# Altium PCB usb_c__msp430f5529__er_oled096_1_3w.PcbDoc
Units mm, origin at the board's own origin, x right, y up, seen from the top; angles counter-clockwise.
Board outline 82 x 52 mm, 2 copper layers (Top, Bottom), stack 0 mm thick; 33 components, 35 nets, 214 pads, 89 vias.
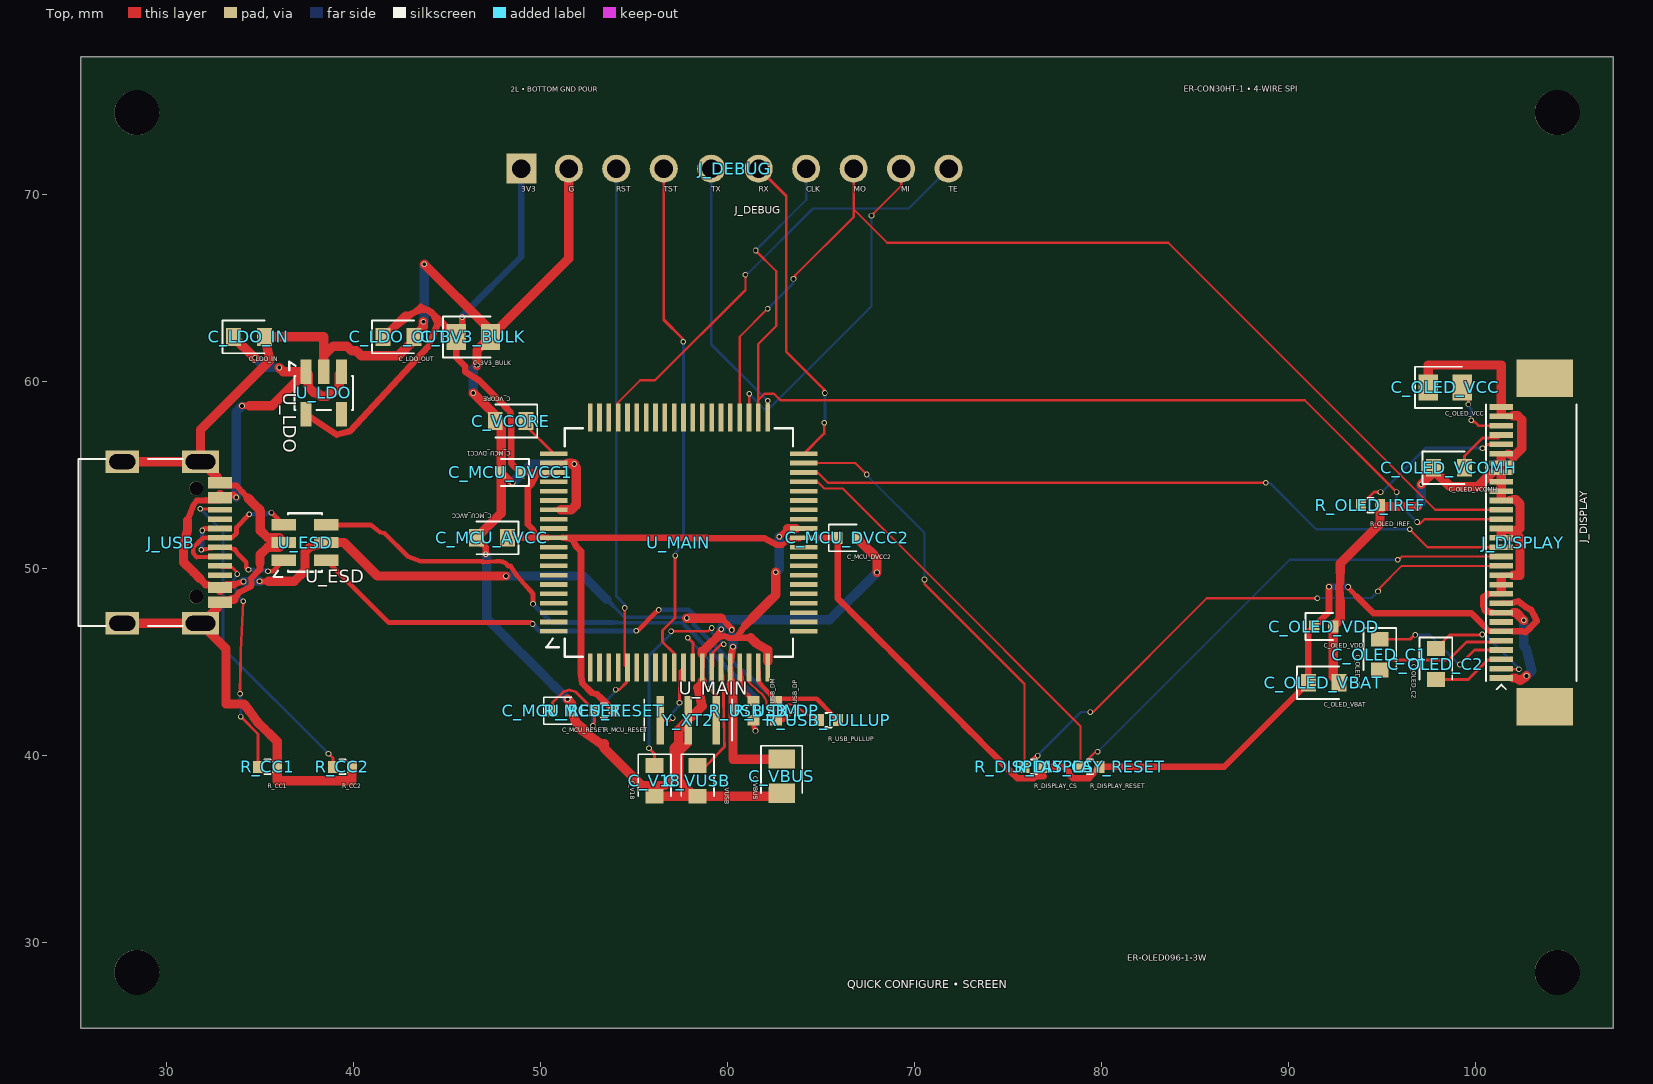
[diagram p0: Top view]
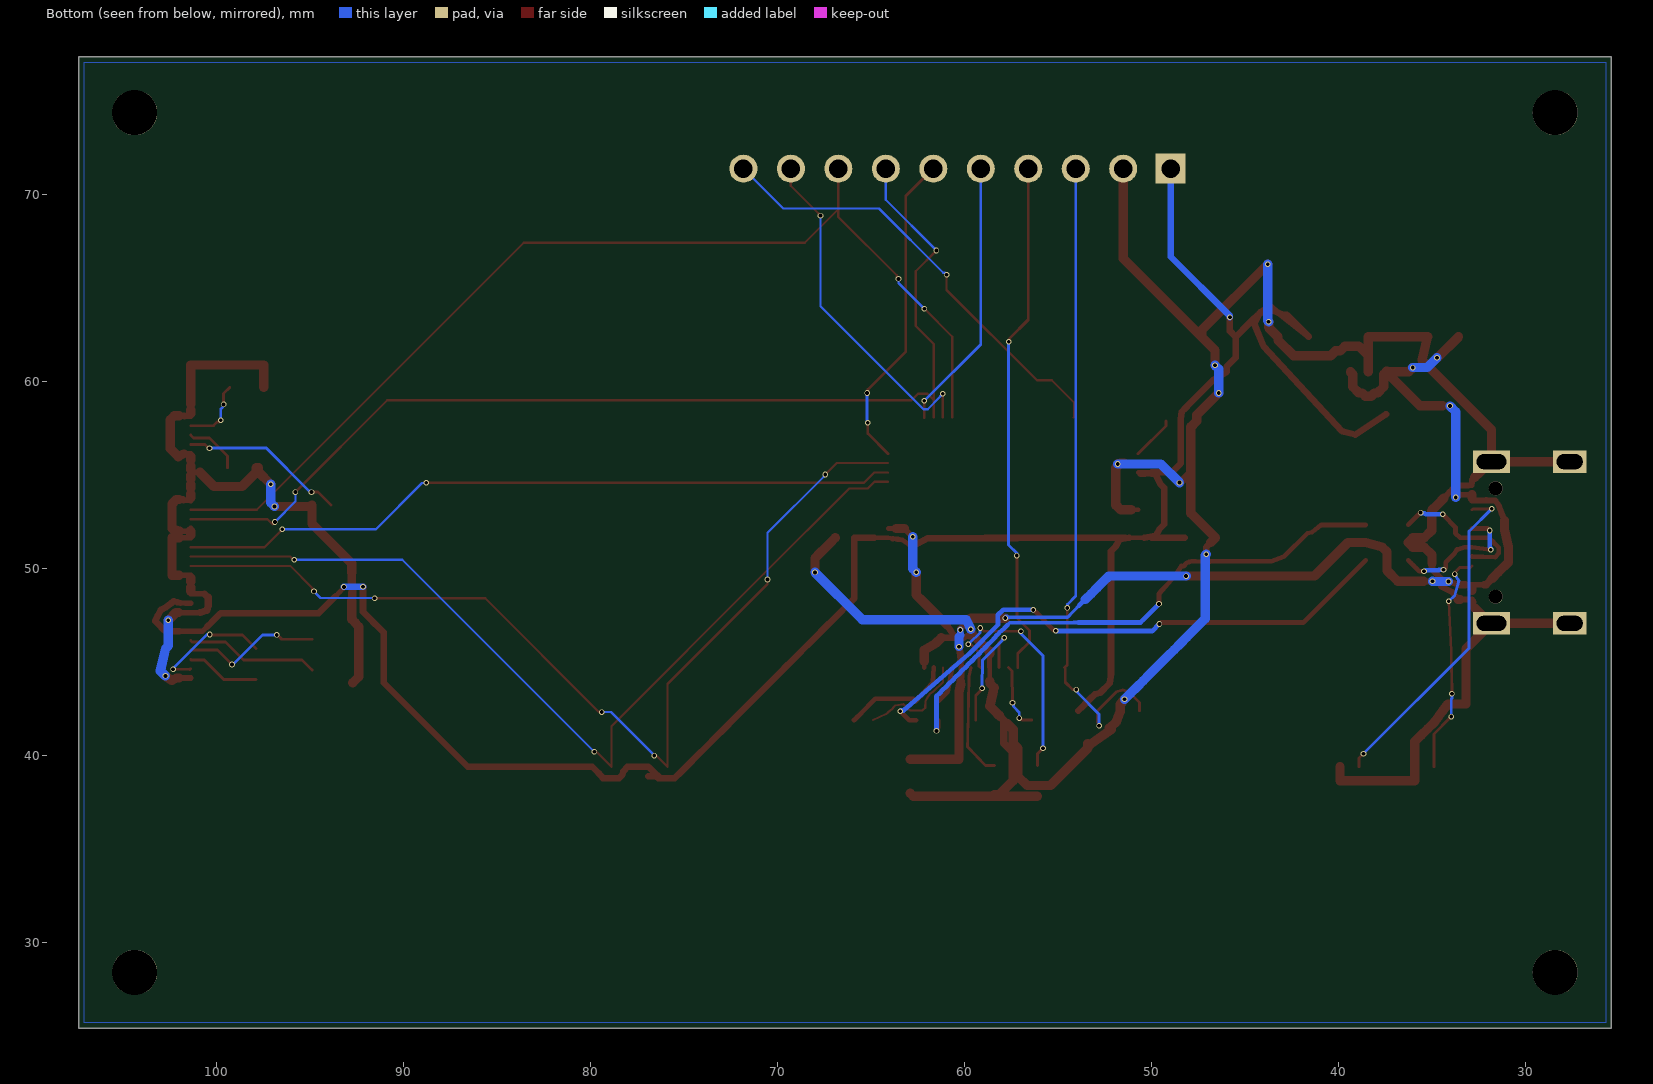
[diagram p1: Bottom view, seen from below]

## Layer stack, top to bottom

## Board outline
25.4,77.4 107.4,77.4 107.4,25.4 25.4,25.4

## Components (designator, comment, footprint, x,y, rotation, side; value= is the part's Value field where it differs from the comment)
C_3V3_BULK "" TSCIRCUIT-2.8500x1.4000mm 46.4,62.4 r0 top
C_LDO_IN "" TSCIRCUIT-2.4500x0.9500mm 34.4,62.4 r0 top
C_LDO_OUT "" TSCIRCUIT-2.4500x0.9500mm 42.4,62.4 r0 top
C_MCU_AVCC "" TSCIRCUIT-2.4500x0.9500mm 47.4,51.65 r180 top
C_MCU_DVCC1 "" TSCIRCUIT-1.5600x0.6400mm 48.4,55.15 r180 top
C_MCU_DVCC2 "" TSCIRCUIT-1.5600x0.6400mm 66.4,51.65 r0 top
C_MCU_RESET "" TSCIRCUIT-1.5600x0.6400mm 51.15,42.4 r0 top
C_OLED_C1 "" TSCIRCUIT-0.9500x2.4500mm 94.9,45.4 r270 top
C_OLED_C2 "" TSCIRCUIT-0.9500x2.4500mm 97.9,44.9 r270 top
C_OLED_VBAT "" TSCIRCUIT-2.4500x0.9500mm 91.9,43.9 r0 top
C_OLED_VCC "" TSCIRCUIT-2.8500x1.4000mm 98.4,59.7 r0 top
C_OLED_VCOMH "" TSCIRCUIT-2.4500x0.9500mm 98.6,55.4 r0 top
C_OLED_VDD "" TSCIRCUIT-1.5600x0.6400mm 91.9,46.9 r0 top
C_V18 "" TSCIRCUIT-0.9500x2.4500mm 56.1,38.65 r270 top
C_VBUS "" TSCIRCUIT-1.4000x2.8500mm 62.9,38.9 r270 top
C_VCORE "" TSCIRCUIT-2.4500x0.9500mm 48.4,57.9 r180 top
C_VUSB "" TSCIRCUIT-0.9500x2.4500mm 58.4,38.65 r270 top
J_DEBUG "" TSCIRCUIT-24.3600x1.5000mm 60.4,71.4 r0 top
J_DISPLAY "" TSCIRCUIT-4.4500x19.5800mm 103,51.4 r90 top
J_USB "" TSCIRCUIT-6.7732x9.8502mm 30.113,51.4 r90 top
R_CC1 "" TSCIRCUIT-1.5600x0.6400mm 35.4,39.4 r0 top
R_CC2 "" TSCIRCUIT-1.5600x0.6400mm 39.4,39.4 r0 top
R_DISPLAY_CS "" TSCIRCUIT-1.5600x0.6400mm 76.4,39.4 r0 top
R_DISPLAY_RESET "" TSCIRCUIT-1.5600x0.6400mm 79.4,39.4 r0 top
R_MCU_RESET "" TSCIRCUIT-1.5600x0.6400mm 53.4,42.4 r0 top
R_OLED_IREF "" TSCIRCUIT-1.5600x0.6400mm 94.4,53.4 r0 top
R_USB_DM "" TSCIRCUIT-0.6400x1.5600mm 61.4,42.4 r90 top
R_USB_DP "" TSCIRCUIT-0.6400x1.5600mm 62.6,42.4 r90 top
R_USB_PULLUP "" TSCIRCUIT-1.5600x0.6400mm 65.4,41.9 r0 top
U_ESD "" TSCIRCUIT-3.6000x2.5000mm 37.4,51.4 r0 top
U_LDO "" TSCIRCUIT-2.5000x3.6000mm 38.4,59.4 r270 top
U_MAIN "" TSCIRCUIT-14.8500x14.8500mm 57.4,51.4 r0 top
Y_XT2 "" TSCIRCUIT-3.4000x2.6000mm 57.9,41.9 r270 top

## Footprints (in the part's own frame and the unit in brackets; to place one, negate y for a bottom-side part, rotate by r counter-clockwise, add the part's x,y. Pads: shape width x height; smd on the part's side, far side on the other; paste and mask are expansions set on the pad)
TSCIRCUIT-0.6400x1.5600mm [mm]
  rect 0.54x0.64 smd: 1(-0.51,0) 2(0.51,0)
  silkscreen extent -0.15,-0.38 0.15,0.38
TSCIRCUIT-0.9500x2.4500mm [mm]
  rect 0.8x0.95 smd: 1(-0.825,0) 2(0.825,0)
  silkscreen extent -1.42,-0.87 0.82,0.87
TSCIRCUIT-1.4000x2.8500mm [mm]
  rect 1.025x1.4 smd: 1(-0.913,0) 2(0.913,0)
  silkscreen extent -1.62,-1.1 0.91,1.1
TSCIRCUIT-1.5600x0.6400mm [mm]
  rect 0.54x0.64 smd: 1(-0.51,0) 2(0.51,0)
  silkscreen extent -0.98,-0.72 0.51,0.72
TSCIRCUIT-2.4500x0.9500mm [mm]
  rect 0.8x0.95 smd: 1(-0.825,0) 2(0.825,0)
  silkscreen extent -1.43,-0.87 0.82,0.87
TSCIRCUIT-2.5000x3.6000mm [mm]
  rect 1.325x0.6 smd: 1(-1.137,-0.95) 2(-1.137,0) 3(-1.137,0.95) 4(1.138,0.95) 5(1.138,-0.95)
  silkscreen extent -1.69,-1.84 0.91,1.56
TSCIRCUIT-2.8500x1.4000mm [mm]
  rect 1.025x1.4 smd: 1(-0.913,0) 2(0.913,0)
  silkscreen extent -1.63,-1.1 0.91,1.1
TSCIRCUIT-3.4000x2.6000mm [mm]
  rect 2.6x0.4 smd: 1(0,1.5) 2(0,0) 3(0,-1.5)
  silkscreen extent -1.1,-2.35 1.1,2.35
TSCIRCUIT-3.6000x2.5000mm [mm]
  rect 1.325x0.6 smd: 1(-1.137,-0.95) 2(-1.137,0) 3(-1.137,0.95) 4(1.138,0.95) 5(1.138,0) 6(1.138,-0.95)
  silkscreen extent -1.69,-1.84 0.91,1.56
TSCIRCUIT-4.4500x19.5800mm [mm]
  rect 0.3x1.25 smd: 1(-7.25,1.6) 2(-6.75,1.6) 3(-6.25,1.6) 4(-5.75,1.6) 5(-5.25,1.6) 6(-4.75,1.6) 7(-4.25,1.6) 8(-3.75,1.6) 9(-3.25,1.6) 10(-2.75,1.6) 11(-2.25,1.6) 12(-1.75,1.6) 13(-1.25,1.6) 14(-0.75,1.6) 15(-0.25,1.6) 16(0.25,1.6) 17(0.75,1.6) 18(1.25,1.6) 19(1.75,1.6) 20(2.25,1.6) 21(2.75,1.6) 22(3.25,1.6) 23(3.75,1.6) 24(4.25,1.6) 25(4.75,1.6) 26(5.25,1.6) 27(5.75,1.6) 28(6.25,1.6) 29(6.75,1.6) 30(7.25,1.6)
  rect 2x3 smd: 31(8.79,-0.725) 32(-8.79,-0.725)
  silkscreen extent -7.85,-2.43 7.4,2.42
TSCIRCUIT-6.7732x9.8502mm [mm]
  rect 0.3x1.3 smd: 1(-3.35,-2.737) 2(-3.05,-2.737) 3(-2.55,-2.737) 4(-2.25,-2.737) 5(-1.75,-2.737) 6(-1.25,-2.737) 7(-0.75,-2.737) 8(-0.25,-2.737) 9(0.25,-2.737) 10(0.75,-2.737) 11(1.25,-2.737) 12(1.75,-2.737) 13(2.55,-2.737) 14(2.25,-2.737) 15(3.35,-2.737) 16(3.05,-2.737)
  rect 1.2x2 hole 0.8 slot 1.6 at 90 deg: 17(-4.325,-1.693) 18(4.325,-1.693)
  rect 1.2x1.8 hole 0.8 slot 1.4 at 90 deg: 19(4.325,2.487) 20(-4.325,2.487)
  round 0.75 hole 0.75 unplated: NPTH-1(-2.9,-1.468) NPTH-2(2.9,-1.468)
  silkscreen extent -4.47,-0.75 4.47,4.83
TSCIRCUIT-14.8500x14.8500mm [mm]
  rect 1.475x0.25 smd: 1(-6.687,-4.75) 2(-6.687,-4.25) 3(-6.687,-3.75) 4(-6.687,-3.25) 5(-6.687,-2.75) 6(-6.687,-2.25) 7(-6.687,-1.75) 8(-6.687,-1.25) 9(-6.687,-0.75) 10(-6.687,-0.25) 11(-6.687,0.25) 12(-6.687,0.75) 13(-6.687,1.25) 14(-6.687,1.75) 15(-6.687,2.25) 16(-6.687,2.75) 17(-6.687,3.25) 18(-6.687,3.75) 19(-6.687,4.25) 20(-6.687,4.75) 41(6.687,4.75) 42(6.687,4.25) 43(6.687,3.75) 44(6.687,3.25) 45(6.687,2.75) 46(6.687,2.25) 47(6.687,1.75) 48(6.687,1.25) 49(6.687,0.75) 50(6.687,0.25) 51(6.687,-0.25) 52(6.687,-0.75) 53(6.687,-1.25) 54(6.687,-1.75) 55(6.687,-2.25) 56(6.687,-2.75) 57(6.687,-3.25) 58(6.687,-3.75) 59(6.687,-4.25) 60(6.687,-4.75)
  rect 0.25x1.475 smd: 21(-4.75,6.687) 22(-4.25,6.687) 23(-3.75,6.687) 24(-3.25,6.687) 25(-2.75,6.687) 26(-2.25,6.687) 27(-1.75,6.687) 28(-1.25,6.687) 29(-0.75,6.687) 30(-0.25,6.687) 31(0.25,6.687) 32(0.75,6.687) 33(1.25,6.687) 34(1.75,6.687) 35(2.25,6.687) 36(2.75,6.687) 37(3.25,6.687) 38(3.75,6.687) 39(4.25,6.687) 40(4.75,6.687) 61(4.75,-6.687) 62(4.25,-6.687) 63(3.75,-6.687) 64(3.25,-6.687) 65(2.75,-6.687) 66(2.25,-6.687) 67(1.75,-6.687) 68(1.25,-6.687) 69(0.75,-6.687) 70(0.25,-6.687) 71(-0.25,-6.687) 72(-0.75,-6.687) 73(-1.25,-6.687) 74(-1.75,-6.687) 75(-2.25,-6.687) 76(-2.75,-6.687) 77(-3.25,-6.687) 78(-3.75,-6.687) 79(-4.25,-6.687) 80(-4.75,-6.687)
  silkscreen extent -7.09,-6.11 6.11,6.11
TSCIRCUIT-24.3600x1.5000mm [mm]
  rect 1.6x1.6 hole 1: 1(-11.43,0)
  round 1.5 hole 1: 2(-8.89,0) 3(-6.35,0) 4(-3.81,0) 5(-1.27,0) 6(1.27,0) 7(3.81,0) 8(6.35,0) 9(8.89,0) 10(11.43,0)

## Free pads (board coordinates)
  round 2.4 hole 2.4 unplated: NPTH-3(28.4,28.4) NPTH-4(104.4,28.4) NPTH-5(28.4,74.4) NPTH-6(104.4,74.4)

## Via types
v1: diameter 0.3, hole 0.2, Top to Bottom, 89 vias

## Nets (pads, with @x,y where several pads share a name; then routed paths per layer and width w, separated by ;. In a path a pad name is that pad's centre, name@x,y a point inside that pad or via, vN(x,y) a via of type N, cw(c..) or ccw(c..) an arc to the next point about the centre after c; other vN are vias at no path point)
".J_DEBUG > .pin4 to .U_MAIN > .pin71": J_DEBUG.4 U_MAIN.71 | length 27.8
  Top w0.15: J_DEBUG.4 56.59,63.315 57.59,62.315 57.59,62.192 v1(57.639,62.143) ; U_MAIN.71 57.15,45.461 56.53,46.081 56.528,46.686 57.199,47.355 v1(57.2,50.7)
  Bottom w0.15: v1(57.2,50.7) 57.2,50.826 57.639,51.265 v1(57.639,62.143)
".J_DEBUG > .pin5 to .U_MAIN > .pin40": J_DEBUG.5 U_MAIN.40 | length 14.6
  Top w0.15: U_MAIN.40 62.158,58.095 v1(62.158,58.989)
  Bottom w0.15: J_DEBUG.5 59.13,61.995 62.105,59.019 62.128,59.019 v1(62.158,58.989)
".J_DEBUG > .pin6 to .U_MAIN > .pin41": J_DEBUG.6 U_MAIN.41 | length 17.2
  Top w0.15: J_DEBUG.6 63.149,69.921 63.149,61.763 63.149,61.601 65.156,59.594 65.156,59.458 v1(65.214,59.4) ; U_MAIN.41 65.172,57.234 v1(65.172,57.801)
  Bottom w0.15: v1(65.172,57.801) 65.192,57.821 65.192,57.911 65.214,57.933 v1(65.214,59.4)
".J_DISPLAY > .pin2 to .C_OLED_C2 > .pin1": C_OLED_C2.1 J_DISPLAY.2 | length 6.5
  Top w0.15: C_OLED_C2.1 98.622,46.447 100.351,46.447 v1(100.383,46.479) ; J_DISPLAY.2 101.45,44.6 v1(102.339,44.621)
  Bottom w0.15: v1(100.383,46.479) 100.521,46.479 102.366,44.634 v1(102.339,44.621)
".J_DISPLAY > .pin3 to .C_OLED_C2 > .pin2": C_OLED_C2.2 J_DISPLAY.3 | length 3.9
  Top w0.15: C_OLED_C2.2 99.629,44.075 100.672,45.117 101.367,45.117 J_DISPLAY.3
".J_DISPLAY > .pin4 to .C_OLED_C1 > .pin1": C_OLED_C1.1 J_DISPLAY.4 | length 7.6
  Top w0.15: C_OLED_C1.1 96.527,46.225 96.775,46.472 v1(96.79,46.457) ; v1(99.189,44.872) 99.967,45.65 J_DISPLAY.4
  Bottom w0.15: v1(96.79,46.457) 97.549,46.457 99.133,44.873 v1@99.188,44.873
".J_DISPLAY > .pin5 to .C_OLED_C1 > .pin2": C_OLED_C1.2 J_DISPLAY.5 | length 7.2
  Top w0.15: C_OLED_C1.2 95.446,45.121 98.579,45.121 99.539,46.081 101.18,46.081 101.331,46.081 J_DISPLAY.5
".J_DISPLAY > .pin26 to .R_OLED_IREF > .pin1": J_DISPLAY.26 R_OLED_IREF.1 | length 8.9
  Top w0.15: R_OLED_IREF.1 94.588,54.098 v1(94.934,54.098) ; v1(100.393,56.449) 100.425,56.481 100.47,56.481 100.64,56.65 J_DISPLAY.26
  Bottom w0.15: v1(94.934,54.098) 94.998,54.162 95.07,54.162 97.357,56.449 v1(100.393,56.449)
".J_DISPLAY > .pin27 to .C_OLED_VCOMH > .pin2": C_OLED_VCOMH.2 J_DISPLAY.27 | length 3.1
  Top w0.15: C_OLED_VCOMH.2 99.425,56.026 100.397,56.997 101.247,56.997 J_DISPLAY.27
".J_DISPLAY > .pin28 to .C_OLED_VCC > .pin2": C_OLED_VCC.2 J_DISPLAY.28 | length 3.7
  Top w0.15: C_OLED_VCC.2 99.638,59.375 v1(99.638,58.79) ; v1(99.795,57.941) 99.884,57.852 99.984,57.852 100.185,57.65 J_DISPLAY.28
  Bottom w0.15: v1(99.638,58.79) 99.679,58.687 99.679,58.642 99.795,58.527 v1(99.795,57.941)
DISPLAY_CS_N: J_DISPLAY.13 R_DISPLAY_CS.1 U_MAIN.42 | length 52.8
  Top w0.12: U_MAIN.42 66.84,55.65 v1(67.454,55.036) ; v1(70.539,49.42) 70.539,49.183 75.89,43.832 R_DISPLAY_CS.1 76.49,40 v1(76.6,40) ; v1(79.408,42.328) 79.427,42.347 79.578,42.347 85.647,48.416 v1(91.562,48.416) ; v1(94.803,48.784) 94.892,48.873 94.892,48.963 96.078,50.15 J_DISPLAY.13
  Bottom w0.12: v1(67.454,55.036) 67.536,54.954 67.536,54.922 70.539,51.92 v1(70.539,49.42) ; v1(76.6,40) 76.612,40.012 76.612,40.032 78.908,42.328 v1(79.408,42.328) ; v1(91.562,48.416) 91.583,48.437 91.698,48.437 94.456,48.437 v1(94.803,48.784)
DISPLAY_DC: J_DISPLAY.15 U_MAIN.43 | length 39
  Top w0.12: U_MAIN.43 64.094,55.144 64.833,55.144 65.377,54.6 v1(88.8,54.6) ; v1(96.495,52.111) 96.533,52.073 97.456,51.15 J_DISPLAY.15
  Bottom w0.12: v1(88.8,54.6) 88.821,54.579 89.018,54.579 91.486,52.111 v1(96.495,52.111)
DISPLAY_MISO: J_DEBUG.9 U_MAIN.38 | length 18.5
  Top w0.12: U_MAIN.38 61.163,58.1 v1(61.163,59.354) ; v1(67.706,68.889) 67.819,69.002 67.819,69.009 69.29,70.481 J_DEBUG.9
  Bottom w0.12: v1(61.163,59.354) 61.308,59.209 61.308,59.192 61.972,58.529 62.199,58.529 67.706,64.036 v1(67.706,68.889)
DISPLAY_MOSI: J_DEBUG.8 J_DISPLAY.19 U_MAIN.37 | length 59.3
  Top w0.12: U_MAIN.37 60.65,62.404 v1(62.146,63.9) ; v1(63.531,65.503) 63.631,65.603 63.631,65.692 66.75,68.812 J_DEBUG.8 66.75,69.234 68.541,67.443 83.577,67.443 97.87,53.15 J_DISPLAY.19
  Bottom w0.12: v1(62.146,63.9) 62.271,64.025 62.274,64.025 63.531,65.282 v1(63.531,65.503)
DISPLAY_RESET_N: J_DISPLAY.14 R_DISPLAY_RESET.1 U_MAIN.44 | length 49.6
  Top w0.12: U_MAIN.44 64.817,54.65 65.177,54.29 66.173,54.29 70.734,49.73 78.89,41.574 R_DISPLAY_RESET.1 79.692,40.202 v1(79.801,40.202) ; v1(95.856,50.477) 95.903,50.524 95.953,50.524 96.079,50.65 J_DISPLAY.14
  Bottom w0.12: v1(79.801,40.202) 79.803,40.204 90.076,50.477 v1(95.856,50.477)
DISPLAY_SCLK: J_DEBUG.7 J_DISPLAY.18 U_MAIN.39 | length 59.4
  Top w0.12: v1(61.502,67.021) 62.608,65.915 62.608,62.98 61.65,62.022 U_MAIN.39 61.65,59.028 61.979,59.357 62.485,59.357 62.833,59.009 90.887,59.009 v1(95.797,54.099) ; v1(96.893,52.496) 97.017,52.372 97.294,52.65 J_DISPLAY.18
  Bottom w0.12: v1(61.502,67.021) 61.496,67.027 64.21,69.742 J_DEBUG.7 ; v1(95.797,54.099) 95.798,54.098 95.798,54.041 95.798,53.591 v1(96.893,52.496)
DISPLAY_TE: J_DEBUG.10 U_MAIN.24 | length 24.2
  Top w0.12: U_MAIN.24 54.128,58.109 54.128,58.875 55.335,60.083 56.126,60.083 60.958,64.915 v1(60.958,65.728)
  Bottom w0.12: v1(60.958,65.728) 61.06,65.83 61.138,65.83 64.575,69.268 64.714,69.268 69.698,69.268 J_DEBUG.10
GND: C_3V3_BULK.2 C_LDO_IN.2 C_LDO_OUT.2 C_MCU_AVCC.2 C_MCU_DVCC1.2 C_MCU_DVCC2.2 C_MCU_RESET.2 C_OLED_VBAT.2 C_OLED_VCC.1 C_OLED_VCOMH.1 C_OLED_VDD.2 C_V18.2 C_VBUS.2 C_VCORE.2 C_VUSB.2 J_DEBUG.2 J_DISPLAY.1 J_DISPLAY.8 J_DISPLAY.10 J_DISPLAY.11 J_DISPLAY.12 J_DISPLAY.16 J_DISPLAY.17 J_DISPLAY.20 J_DISPLAY.21 J_DISPLAY.22 J_DISPLAY.23 J_DISPLAY.24 J_DISPLAY.25 J_DISPLAY.29 J_DISPLAY.30 J_USB.1 J_USB.2 J_USB.15 J_USB.16 J_USB.17 J_USB.18 J_USB.19 J_USB.20 R_CC1.2 R_CC2.2 R_OLED_IREF.2 U_ESD.2 U_LDO.2 U_MAIN.14 U_MAIN.19 U_MAIN.49 U_MAIN.61 U_MAIN.68 Y_XT2.2 | length 220.7
  Top w0.25: U_MAIN.14 U_MAIN.14@51.088,53.15 ; U_MAIN.68@58.65,43.975 58.65,44.056 58.65,44.15 58.65,44.243 58.65,44.337 58.65,44.431 58.65,44.525 58.65,44.618 U_MAIN.68 ; U_MAIN.68 58.65,45.087 58.65,45.45 U_MAIN.68 ; U_MAIN.68@58.691,45.45 58.682,45.095 58.682,44.744 U_MAIN.68 ; U_MAIN.61 U_MAIN.61@62.15,45.055 ; U_MAIN.49@63.658,52.15 U_MAIN.49 ; U_MAIN.19 51.45,55.65 51.369,55.65 51.275,55.65 51.181,55.65 51.088,55.65 50.994,55.65 50.9,55.65 50.806,55.65 U_MAIN.19
  Top w0.275: J_USB.1@32.849,48.2 J_USB.2
  Top w0.288: J_USB.15@32.849,54.6 J_USB.16 J_USB.16@32.945,54.461
  Top w0.3: J_USB.1@32.699,47.9 J_USB.1 J_USB.2@32.849,48.2 ; 32.699,54.9 J_USB.15 J_USB.16@32.849,54.6 ; J_USB.2 32.945,48.339 33.037,48.35 33.13,48.35 33.224,48.35 33.318,48.35 33.412,48.35 33.499,48.35 ; J_USB.16@32.945,54.461 33.037,54.45 J_USB.16@33.318,54.45 ; 100.65,48.65 101.133,48.65 J_DISPLAY.10 101.4,48.8 ; J_DISPLAY.8@100.9,47.65 101.132,47.65 J_DISPLAY.8 101.494,47.65 101.588,47.65 101.681,47.65 101.775,47.65 101.869,47.65 101.963,47.65 102.025,47.65 102.056,47.65 ; J_DISPLAY.23@100.9,55.15 J_DISPLAY.23 ; J_DISPLAY.1 101.494,44.15 101.588,44.15 101.681,44.15 101.775,44.15 101.869,44.15 101.963,44.15 102.025,44.15 ; J_DISPLAY.11@101.4,49 J_DISPLAY.11 J_DISPLAY.11@101.4,49.3 ; J_DISPLAY.12@101.4,49.5 J_DISPLAY.12 101.408,49.642 101.734,49.642 J_DISPLAY.12@102.025,49.642 ; J_DISPLAY.16@101.4,51.8 J_DISPLAY.16 J_DISPLAY.16@102.025,51.65 ; 101.4,52 J_DISPLAY.17 101.6,52 102,52 ; 101.4,53.8 J_DISPLAY.20 J_DISPLAY.20@101.783,53.673 ; J_DISPLAY.21@101.4,54 J_DISPLAY.21 J_DISPLAY.21@101.4,54.3 ; J_DISPLAY.22@101.4,54.5 J_DISPLAY.22 101.4,54.8 ; J_DISPLAY.23@101.4,55 J_DISPLAY.23 ; 101.4,55.3 J_DISPLAY.23 ; J_DISPLAY.24@101.4,55.5 J_DISPLAY.24 101.4,55.8 ; J_DISPLAY.25@101.4,56 J_DISPLAY.25 J_DISPLAY.25@101.741,56.15 ; 101.4,58.3 J_DISPLAY.29 J_DISPLAY.29@101.728,58.166 ; J_DISPLAY.30@101.4,58.5 J_DISPLAY.30 101.4,58.8 ; J_DISPLAY.20@101.806,53.697 J_DISPLAY.20@102.025,53.697
  Top w0.31: 34.519,49.48 34.542,49.144
  Top w0.312: J_USB.16@33.318,54.45 33.599,54.45 33.744,54.447 34.009,54.132 ; 33.9,48.744 34.212,48.9 34.525,49.056 34.542,49.144 ; 59.166,46.11 59.416,46.434 v1(59.666,46.757) ; 59.486,46.297 59.837,46.4 60.046,46.296 ; v1(62.774,51.701) 62.996,51.923 63.002,51.923 63.229,52.15
  Top w0.325: 33.597,48.361 33.9,48.744 ; 34.009,54.132 34.346,53.784 ; 34.519,49.48 34.758,49.727 ; v1@48.426,54.614 v1(48.5,54.605) ; 58.65,45.45 58.65,45.462 58.929,45.74 59.207,46.019 59.486,46.297 ; 59.421,46.296 59.837,46.4 60.046,46.296 ; 60.711,46.637 60.462,46.296 60.046,46.296 ; 60.81,46.297 60.368,46.297 60.046,46.296
  Top w0.35: 33.597,48.361 33.599,48.35 ; 34.758,49.727 34.997,49.974 ; C_MCU_AVCC.2@46.821,51.403 47.068,51.157 v1(47.068,50.771) ; 60.711,46.637 60.96,46.978 ; 60.81,46.297 61.251,46.297
  Top w0.359: J_DISPLAY.29@101.728,58.166 J_DISPLAY.29@102.025,58.18
  Top w0.375: 34.993,50.295 34.997,49.974 ; 100.462,48.025 100.525,47.775 J_DISPLAY.8@100.9,47.65 ; 100.462,48.462 100.65,48.65
  Top w0.376: J_DISPLAY.20@101.783,53.673 J_DISPLAY.20@101.806,53.697
  Top w0.4: C_MCU_DVCC1.2 48.158,54.882 v1@48.426,54.614 ; 57.4,40.15 57.9,40.65 Y_XT2.2 ; Y_XT2.2@57.7,41.7 Y_XT2.2 ; Y_XT2.2@58.1,42.101 Y_XT2.2 ; 100.462,48.025 100.462,48.462
  Top w0.425: 58.65,45.594 59.166,46.11 ; 58.712,45.588 59.421,46.296
  Top w0.437: 92.752,48.68 92.723,49.067 92.784,49.285
  Top w0.45: 58.691,45.45 58.692,45.462 58.712,45.588 ; 60.96,46.978 61.284,47.302 ; 92.752,48.68 92.782,48.293
  Top w0.475: 33.499,48.35 33.505,48.35 33.599,48.35 ; 58.416,43.634 58.634,43.853 58.636,43.962 58.65,43.974 ; 92.784,49.285 92.785,49.781 ; J_DISPLAY.25@101.741,56.15 102.056,55.994 ; 102.025,44.15 102.056,44.15 ; 102.056,47.65 102.15,47.65
  Top w0.5: J_USB.20 J_USB.17 ; J_USB.19 J_USB.18 ; J_USB.1@32.699,47.9 32.474,47.675 31.874,47.075 J_USB.17 ; 32.699,54.9 32.474,55.125 31.874,55.725 J_USB.18 ; 34.346,53.784 34.683,53.436 35.012,53.108 35.012,52.187 35.012,52.038 35.4,51.65 36.013,51.65 U_ESD.2 36.013,51.15 35.4,51.15 34.989,50.739 34.989,50.615 34.993,50.295 ; R_CC2.2 39.91,38.65 35.91,38.65 R_CC1.2 35.91,39.851 35.91,40.302 35.909,40.753 35.565,41.094 35.22,41.436 34.875,41.777 34.628,42.105 34.381,42.432 34.134,42.759 33.168,42.759 33.168,45.713 J_USB.17 ; v1(43.732,63.208) 43.732,62.907 C_LDO_OUT.2 43.225,62.225 42.4,61.4 40.4,61.4 40.15,61.65 39.9,61.65 39.65,61.9 38.9,61.9 38.4,61.4 U_LDO.2 38.4,62.4 C_LDO_IN.2 35.525,61.15 31.806,57.431 J_USB.18 ; v1(43.783,66.292) 47.313,62.763 C_3V3_BULK.2 ; v1(46.4,59.4) 47.575,58.225 C_VCORE.2 47.89,57.585 47.89,57.098 47.89,56.611 47.89,56.124 47.89,55.637 C_MCU_DVCC1.2 47.89,52.965 C_MCU_AVCC.2 C_MCU_AVCC.2@46.821,51.403 ; v1(46.602,60.884) 46.602,61.69 C_3V3_BULK.2 ; U_MAIN.14@51.088,53.15 51.65,53.15 51.9,53.4 51.9,55.4 51.65,55.65 51.45,55.65 51.463,55.65 51.663,55.65 51.698,55.615 51.785,55.615 v1(51.8,55.6) ; v1(51.439,43.012) 51.557,42.894 51.557,42.857 51.66,42.754 C_MCU_RESET.2 51.78,42.088 51.9,41.775 52.25,41.475 52.15,41.4 53.3,40.575 53.375,40.65 53.4,40.65 53.4,40.4 55.4,38.4 56.65,38.4 57.15,38.9 57.15,40.4 57.4,40.65 57.4,41.4 57.7,41.7 ; J_DEBUG.2 51.51,66.597 C_3V3_BULK.2 ; C_V18.2 C_VUSB.2 ; 57.4,40.15 57.4,38.65 58.15,37.9 58.4,37.9 C_VUSB.2 ; 58.1,42.101 58.148,42.15 58.396,42.4 58.645,42.65 58.568,42.978 58.492,43.306 58.416,43.634 ; 58.65,45.45 58.65,45.594 ; 61.251,46.297 61.551,45.998 62.15,45.65 U_MAIN.61@62.15,45.055 ; 61.284,47.302 61.607,47.626 61.931,47.949 62.254,48.273 62.578,48.596 62.578,48.998 62.578,49.4 v1(62.578,49.802) ; C_VBUS.2 62.737,37.825 C_VUSB.2 ; 63.229,52.15 U_MAIN.49@63.658,52.15 ; C_MCU_DVCC2.2 67.182,51.377 67.455,51.105 67.727,50.832 68,50.56 68,50.18 v1(68,49.8) ; C_OLED_VBAT.2 92.41,44.215 C_OLED_VDD.2 92.595,47.1 92.78,47.301 92.781,47.797 92.782,48.293 ; 92.785,49.781 92.786,50.278 94.91,52.402 R_OLED_IREF.2 94.984,53.326 v1(96.914,53.326) ; v1(97.112,54.512) 97.775,55.175 C_OLED_VCOMH.1 97.9,55.4 97.9,55.15 98.65,54.4 100.15,54.4 J_DISPLAY.23@100.9,55.15 ; C_OLED_VCC.1 97.488,60.9 101.4,60.9 101.4,58.8 ; 101.4,48.8 101.4,49 ; 101.4,49.3 J_DISPLAY.12@101.4,49.5 ; 101.4,51.8 101.4,52 ; 101.4,53.8 101.4,54 ; 101.4,54.3 J_DISPLAY.22@101.4,54.5 ; 101.4,54.8 J_DISPLAY.23@101.4,55 ; 101.4,55.3 101.4,55.5 ; 101.4,55.8 J_DISPLAY.25@101.4,56 ; 101.4,58.3 J_DISPLAY.30@101.4,58.5 ; 102,52 102.4,52.15 102.4,53.462 102.166,53.697 102.025,53.697 ; 102.025,49.642 102.392,49.642 102.4,49.65 102.4,51.65 102.025,51.65 ; 102.025,58.18 102.056,58.181 102.275,58.181 102.494,57.963 102.494,57.58 102.494,57.197 102.494,56.814 102.494,56.431 102.275,56.213 102.056,55.994 ; 102.056,44.15 102.15,44.15 102.4,44.025 v1(102.749,44.264) ; 102.15,47.65 102.186,47.65 v1(102.593,47.244)
  Bottom w0.5: v1(43.732,63.208) 43.783,63.259 v1(43.783,66.292) ; v1(46.4,59.4) 46.4,60.68 46.555,60.835 46.555,60.837 v1(46.602,60.884) ; v1(47.068,50.771) 47.122,50.717 47.122,50.631 47.122,50.159 47.122,49.688 47.122,49.216 47.122,48.744 47.122,48.272 47.122,47.801 47.122,47.329 47.454,46.997 47.786,46.665 48.118,46.333 48.45,46.001 48.782,45.669 49.114,45.337 49.447,45.004 49.779,44.672 50.111,44.34 50.443,44.008 50.775,43.676 51.107,43.344 v1(51.439,43.012) ; v1(48.5,54.605) 49.495,55.6 v1(51.8,55.6) ; v1(59.666,46.757) 59.9,47.275 65.475,47.275 v1(68,49.8) ; v1(62.578,49.802) 62.774,49.998 v1(62.774,51.701) ; v1(96.914,53.326) 96.928,53.34 97.112,53.524 v1(97.112,54.512) ; v1(102.593,47.244) 102.593,45.873 102.748,45.718 103.025,44.525 103.01,44.525 v1(102.749,44.264)
MAIN_RESET: C_MCU_RESET.1 J_DEBUG.3 R_MCU_RESET.1 U_MAIN.76 | length 35.1
  Top w0.15: C_MCU_RESET.1 50.64,42.833 51.217,43.411 51.534,43.507 51.879,43.411 R_MCU_RESET.1 52.89,41.777 52.8,41.687 v1(52.8,41.6) ; v1(54.027,43.533) 54.218,43.533 54.612,43.927 54.612,44.674 U_MAIN.76 54.5,44.862 v1(54.5,47.9)
  Bottom w0.15: v1(52.8,41.6) 52.8,42.21 53.959,43.369 53.959,43.465 v1(54.027,43.533) ; J_DEBUG.3 54.05,48.537 54.5,48.087 v1(54.5,47.9)
MSP_USB_PUR: R_USB_PULLUP.1 U_MAIN.63 | length 5.8
  Top w0.12: U_MAIN.63 61.15,43.919 61.664,43.437 61.848,43.302 62.013,43.076 62.09,42.895 62.104,42.561 62.268,42.419 62.92,42.43 63.035,42.499 63.087,42.573 63.266,42.744 63.701,42.686 63.8,42.585 63.859,42.495 63.964,42.41 64.077,42.324 64.195,42.22 R_USB_PULLUP.1
MSP_V18: C_V18.1 U_MAIN.67 | length 12.8
  Top w0.15: v1(55.8,40.4) 55.835,40.365 56.1,40.1 C_V18.1 ; v1(56.982,46.657) 58.984,46.66 59.155,46.831 59.168,46.831 v1(59.156,46.826) ; U_MAIN.67 59.218,44.78 59.218,45.523 59.645,45.949 v1(59.797,45.958)
  Bottom w0.15: v1(55.8,40.4) 55.8,45.344 57.047,46.592 v1(56.982,46.657) ; v1(59.156,46.826) 59.176,46.567 59.7,46.043 59.7,46.037 v1(59.797,45.958)
MSP_VCORE: C_VCORE.1 U_MAIN.20 | length 2.4
  Top w0.15: C_VCORE.1 49.225,57.638 U_MAIN.20
MSP_VUSB: C_VUSB.1 U_MAIN.66 | length 6.1
  Top w0.15: C_VUSB.1 58.881,39.475 59.834,40.473 59.826,40.926 59.761,44.224 U_MAIN.66
usb-dm-mcu: R_USB_DM.2 U_MAIN.64 | length 2
  Top w0.25: U_MAIN.64 60.9,43.41 R_USB_DM.2
usb-dm-phy: R_USB_DM.1 U_ESD.4 | length 29.6
  Top w0.25: U_ESD.4 38.551,52.337 38.788,52.337 39.025,52.337 39.262,52.337 39.499,52.337 39.736,52.337 39.973,52.337 40.21,52.337 40.447,52.337 40.684,52.337 40.921,52.337 41.083,52.207 41.244,52.078 41.406,51.948 41.65,51.9 42.924,50.631 43.144,50.55 43.363,50.47 43.583,50.39 43.821,50.39 44.059,50.39 44.296,50.39 44.534,50.39 44.772,50.391 45.01,50.391 45.248,50.391 45.486,50.391 45.724,50.391 45.962,50.392 46.199,50.392 46.437,50.392 46.675,50.392 46.913,50.392 46.9,50.35 47.627,50.393 47.865,50.393 47.991,50.357 48.118,50.32 48.282,50.135 48.4,50.15 48.775,49.581 48.939,49.396 49.103,49.211 49.267,49.027 49.432,48.842 49.596,48.657 49.595,48.476 49.595,48.296 v1(49.594,48.115) ; R_USB_DM.1 61.4,41.698 61.4,41.506 61.482,41.424 61.482,41.339 v1(61.5,41.321)
  Bottom w0.188: 54.151,47.12 54.394,47.12 54.637,47.12 54.879,47.12 55.122,47.119 55.365,47.119 55.607,47.119 55.85,47.119 56.093,47.119 56.335,47.119 56.578,47.119 56.821,47.119 57.063,47.119 57.306,47.119 57.549,47.119 57.689,46.995
  Bottom w0.212: 53.909,47.12 54.151,47.12
  Bottom w0.25: v1(49.594,48.115) 49.638,48.071 49.797,47.912 49.955,47.754 50.113,47.596 50.272,47.437 50.43,47.279 50.588,47.121 50.805,47.121 51.022,47.121 51.239,47.121 51.482,47.121 51.725,47.121 51.967,47.12 52.21,47.12 52.453,47.12 52.695,47.12 52.938,47.12 53.181,47.12 53.423,47.12 53.666,47.12 53.909,47.12 ; 57.689,46.995 57.862,46.821 58.149,46.565 58.266,46.432 58.382,46.3 58.555,46.126 58.729,45.952 58.902,45.779 59.075,45.605 59.248,45.431 59.422,45.257 59.595,45.083 59.768,44.91 59.942,44.736 60.115,44.562 60.288,44.388 60.461,44.215 60.635,44.041 60.808,43.867 60.981,43.693 61.154,43.52 61.328,43.346 61.501,43.172 61.501,42.941 61.501,42.709 61.501,42.478 61.5,42.247 61.5,42.015 61.5,41.784 61.5,41.552 v1(61.5,41.321)
usb-dm-port: J_USB.7 J_USB.9 U_ESD.3 | length 7.9
  Top w0.25: J_USB.7 31.609,50.613 31.422,50.833 31.412,51.132 31.729,51.45 31.961,51.65 J_USB.9 33.49,51.65 33.737,51.896 33.737,52.225 34.371,52.859 v1(34.42,52.908) ; v1(35.6,53) 35.613,53 U_ESD.3
  Bottom w0.25: v1(34.42,52.908) 35.326,52.908 35.391,52.974 35.574,52.974 v1(35.6,53)
usb-dp-mcu: R_USB_DP.2 R_USB_PULLUP.2 U_MAIN.62 | length 6
  Top w0.25: U_MAIN.62 61.702,43.909 R_USB_DP.2 62.722,43.039 62.951,43.039 63.179,43.038 63.407,43.038 63.636,43.038 63.864,43.038 64.092,43.037 64.321,43.037 64.549,43.037 64.778,43.032 64.939,42.871 65.101,42.709 65.263,42.547 65.425,42.385 65.586,42.224 65.748,42.062 R_USB_PULLUP.2
usb-dp-phy: R_USB_DP.1 U_ESD.6 | length 30.4
  Top w0.25: U_ESD.6 41.869,47.118 49.407,47.118 49.497,47.118 v1(49.572,47.043) ; v1(55.121,46.683) 55.191,46.683 56.2,47.692 56.218,47.692 v1(56.319,47.793) ; R_USB_DP.1 62.964,41.89 v1(63.445,42.371)
  Bottom w0.25: v1(49.572,47.043) 49.954,46.661 54.912,46.661 55.099,46.661 v1(55.121,46.683) ; v1(56.319,47.793) 57.928,47.796 58.214,47.522 58.204,47.014 59.781,45.421 63.268,42.41 63.406,42.41 v1(63.445,42.371)
usb-dp-port: J_USB.8 J_USB.10 U_ESD.1 | length 7.5
  Top w0.25: v1(31.841,51.01) J_USB.8 33.049,51.15 33.249,51.15 33.65,51.025 33.774,50.825 33.937,50.662 34.099,50.5 34.262,50.337 34.262,50.193 34.262,50.05 34.393,49.919 v1(34.376,49.936) ; v1(31.898,52.041) 32.007,52.15 32.099,52.15 32.349,52.15 32.599,52.15 J_USB.10 ; v1(35.42,49.857) 35.67,49.857 35.818,50.005 35.966,50.153 36.114,50.302 U_ESD.1
  Bottom w0.25: v1(31.841,51.01) 31.828,51.029 31.828,51.071 31.898,51.14 31.898,51.366 31.898,51.591 31.898,51.816 v1(31.898,52.041) ; v1(34.376,49.936) 34.615,49.93 34.854,49.925 35.093,49.919 35.333,49.913 35.379,49.867 35.41,49.867 v1(35.42,49.857)
USB_CC1: J_USB.6 R_CC1.1 | length 12.1
  Top w0.15: J_USB.6 32.933,50.066 33.509,50.066 33.793,49.782 v1(33.776,49.71) ; v1(33.923,43.312) 33.955,45.583 v1(34.09,48.264) ; v1(33.96,42.088) 34.012,42.036 34.89,41.158 R_CC1.1
  Bottom w0.15: v1(33.776,49.71) 33.786,49.681 33.764,49.671 33.55,49.375 33.775,48.567 v1(34.09,48.264) ; v1(33.923,43.312) 33.916,43.295 33.916,43.069 33.96,43.024 v1(33.96,42.088)
USB_CC2: J_USB.12 R_CC2.1 | length 17.8
  Top w0.15: v1(31.799,53.2) 32.799,53.2 J_USB.12 ; v1(38.657,40.105) 38.688,40.074 38.688,40.066 38.89,39.864 R_CC2.1
  Bottom w0.15: v1(31.799,53.2) 31.823,53.176 32.981,52.018 33.018,52.018 33.018,45.744 v1(38.657,40.105)
VBUS5: C_LDO_IN.1 C_VBUS.1 J_USB.3 J_USB.4 J_USB.13 J_USB.14 U_ESD.5 U_LDO.1 U_LDO.3 U_MAIN.65 | length 66.7
  Top w0.25: U_MAIN.65 U_MAIN.65@60.181,45.056
  Top w0.3: 32.086,53.65 32.467,53.65 J_USB.14 32.849,53.8 ; J_USB.4@32.199,49.15 32.474,49.15 J_USB.4 ; J_USB.3@32.849,49 J_USB.4 ; J_USB.13 32.943,53.95 33.037,53.95 33.13,53.95 33.224,53.95 33.318,53.95 33.412,53.95 33.499,53.95 ; J_USB.4@33.211,49.15 J_USB.4
  Top w0.312: 31.261,52.966 31.409,53.357 31.608,53.64
  Top w0.325: 31.113,52.575 31.261,52.966 ; 33.573,49.15 33.841,49.233 v1(34.108,49.316) ; 33.59,53.941 33.606,53.938 v1(33.721,53.812) ; v1(34.961,49.322) 35.441,49.322 ; 59.664,47.355 59.759,47.259 59.994,47.025 60.228,46.791 v1(60.23,46.725)
  Top w0.335: U_MAIN.65 60.176,44.265 U_MAIN.65@60.193,43.975
  Top w0.35: 31.608,53.64 32.086,53.65 ; 33.499,53.95 33.505,53.95 33.59,53.941 ; v1(34.027,58.707) 34.431,58.712
  Top w0.375: U_MAIN.65@60.213,45.4 v1(60.297,45.821)
  Top w0.383: U_MAIN.65@60.181,45.056 U_MAIN.65@60.213,45.4
  Top w0.4: 31.77,49.477 32.099,49.15 J_USB.4@32.199,49.15 ; J_USB.4@33.211,49.15 33.573,49.15
  Top w0.45: U_MAIN.65@60.193,43.975 60.202,43.817
  Top w0.5: 31.113,52.575 31.113,52.086 30.9,51.15 30.9,50.345 31.44,49.805 31.442,49.805 31.77,49.477 ; J_USB.3 J_USB.4@32.849,49 ; J_USB.13@32.849,53.8 J_USB.13 ; C_LDO_IN.1 34.694,61.281 v1(34.724,61.281) ; 34.431,58.712 34.834,58.717 35.63,58.717 U_LDO.1 ; 35.441,49.322 35.921,49.322 36.822,49.322 37.4,49.9 37.4,50.9 37.65,51.15 U_ESD.5 39.01,51.4 39.482,51.4 41.277,49.605 v1(48.146,49.605) ; v1(36.014,60.759) 36.034,60.739 36.236,60.537 U_LDO.1 ; U_LDO.3 39.35,60.517 39.233,60.4 39.233,59.733 38.9,59.4 38.733,59.4 38.567,59.233 38.233,59.233 38.067,59.4 37.9,59.4 37.567,59.733 37.567,60.4 37.4,60.567 37.421,60.567 U_LDO.1 ; v1(57.821,47.355) 59.664,47.355 ; 60.202,43.817 60.294,43.417 60.294,39.813 C_VBUS.1
  Bottom w0.175: 53.854,48.033 54.17,47.718 54.485,47.402 54.949,47.402 55.414,47.402 55.878,47.402 56.342,47.402 56.806,47.402 57.27,47.402 v1@57.734,47.402
  Bottom w0.25: 53.539,48.349 53.854,48.033
  Bottom w0.275: v1@57.734,47.401 57.775,47.401 v1(57.821,47.355)
  Bottom w0.35: 60.214,46.434 v1(60.23,46.725)
  Bottom w0.4: 60.214,46.434 60.297,46.351
  Bottom w0.475: v1(60.297,45.821) 60.297,46.351
  Bottom w0.5: v1(33.721,53.812) 33.721,58.401 v1(34.027,58.707) ; v1(34.108,49.316) 34.955,49.316 v1(34.961,49.322) ; v1(34.724,61.281) 35.245,60.759 v1(36.014,60.759) ; v1(48.146,49.605) 48.605,49.606 49.064,49.606 49.523,49.607 49.982,49.608 50.441,49.608 50.9,49.609 51.359,49.61 51.818,49.61 52.276,49.611 52.592,49.295 52.908,48.98 53.223,48.664 53.539,48.349
VCC_3V3: C_3V3_BULK.1 C_LDO_OUT.1 C_MCU_AVCC.1 C_MCU_DVCC1.1 C_MCU_DVCC2.1 C_OLED_VBAT.1 C_OLED_VDD.1 J_DEBUG.1 J_DISPLAY.6 J_DISPLAY.9 R_DISPLAY_CS.2 R_DISPLAY_RESET.2 R_MCU_RESET.2 U_LDO.5 U_MAIN.11 U_MAIN.18 U_MAIN.50 | length 131.2
  Top w0.25: U_MAIN.18@49.975,55.075 U_MAIN.18@50.125,55.075 ; U_MAIN.18@49.975,55.15 50.056,55.15 50.15,55.15 50.244,55.15 50.337,55.15 50.431,55.15 50.525,55.15 50.619,55.15 U_MAIN.18 50.589,55.027 50.356,55.027 U_MAIN.18@50.343,55.054 ; U_MAIN.11@49.976,51.65 50.057,51.65 50.15,51.65 50.244,51.65 50.338,51.65 50.432,51.65 50.525,51.65 50.619,51.65 U_MAIN.11 ; U_MAIN.11@50.376,51.65 U_MAIN.11 ; U_MAIN.11@51.198,51.65 50.955,51.65 U_MAIN.11 ; U_MAIN.50@63.83,51.61 U_MAIN.50 64.182,51.65 64.276,51.65 64.369,51.65 64.463,51.65 64.557,51.65 64.651,51.65 64.744,51.65 U_MAIN.50@64.825,51.65
  Top w0.252: U_MAIN.11 51.053,51.65 U_MAIN.11@51.394,51.649
  Top w0.262: 62.922,51.269 63.119,51.4 63.316,51.531 ; v1(93.203,49.025) 93.191,48.984 93.419,48.756 93.647,48.528
  Top w0.275: 100.524,46.891 100.765,46.65 J_DISPLAY.6@101.082,46.65
  Top w0.288: 63.316,51.531 63.573,51.571 U_MAIN.50@63.83,51.61 ; J_DISPLAY.9 101.67,48.156 J_DISPLAY.9@101.94,48.162
  Top w0.3: U_MAIN.18@50.125,55.075 U_MAIN.18@50.343,55.054 ; J_DISPLAY.6@101.082,46.65 J_DISPLAY.6
  Top w0.306: J_DISPLAY.6 101.685,46.649 101.97,46.647 J_DISPLAY.6@102.025,46.647
  Top w0.325: 62.659,51.269 62.922,51.269 ; J_DISPLAY.9@101.94,48.162 102.124,48.212
  Top w0.337: 62.425,51.391 62.659,51.269 ; 100.282,47.133 100.524,46.891 ; 102.124,48.212 102.308,48.261
  Top w0.35: U_LDO.5 39.1,57.175 39.8,57.35 44,61.9 44.5,63.1 44.2,63.7 43.6,64 C_LDO_OUT.1 41.81,62.638 42.045,62.876 42.281,63.114 42.516,63.352 42.751,63.59 43.038,63.617 43.6,63.85 44,63.825 44.547,63.359 44.782,63.12 45.017,62.88 45.252,62.64 C_3V3_BULK.1 ; v1(45.8,63.457) 45.8,62.712 C_3V3_BULK.1 ; C_MCU_AVCC.1 49.963,51.65 49.975,51.65 ; 49.975,55.075 49.775,55.075 49.51,54.515 49.313,54.318 49.313,53.994 49.313,53.671 49.313,53.347 49.313,53.023 49.313,52.7 49.313,52.376 49.555,52.134 49.775,51.75 U_MAIN.11@50.376,51.65 ; U_MAIN.18@49.975,55.15 49.963,55.15 C_MCU_DVCC1.1 48.668,55.392 48.426,55.634 48.433,58.005 48.375,58.4 48.184,58.599 47.939,58.844 47.694,59.089 47.449,59.335 47.204,59.58 46.959,59.825 46.714,60.07 45.962,60.539 45.978,60.805 45.733,61.05 45.488,61.295 45.488,61.572 45.488,61.848 45.488,62.124 C_3V3_BULK.1 ; U_MAIN.11@51.198,51.65 51.7,51.575 51.922,51.168 52.163,50.928 52.163,50.584 52.163,50.24 52.163,49.895 52.163,49.551 52.163,49.207 52.163,48.863 52.163,48.519 52.163,48.175 52.163,47.831 52.163,47.487 52.163,47.143 52.163,46.799 52.163,46.455 52.163,46.111 52.163,45.767 52.163,45.423 52.163,45.078 52.163,44.734 52.163,44.39 52.225,43.875 52.75,43.35 53.034,43.276 53.253,43.057 53.472,42.838 53.691,42.619 R_MCU_RESET.2 ; U_MAIN.11@51.394,51.649 51.735,51.649 52.075,51.648 52.416,51.648 52.757,51.648 53.097,51.647 53.438,51.647 53.779,51.646 54.119,51.646 54.46,51.645 54.801,51.645 55.141,51.645 55.482,51.644 55.823,51.644 56.163,51.643 56.504,51.643 56.845,51.643 57.186,51.642 57.526,51.642 57.867,51.641 58.208,51.641 58.548,51.641 58.889,51.64 59.23,51.64 59.57,51.639 59.911,51.639 60.252,51.638 60.592,51.638 60.933,51.638 61.274,51.637 61.614,51.637 61.955,51.636 62.19,51.514 62.425,51.391 ; 64.825,51.65 64.838,51.65 C_MCU_DVCC2.1 65.89,51.327 65.89,51.004 65.89,50.681 65.89,50.358 65.89,50.035 65.89,49.712 65.89,49.389 65.89,49.067 65.89,48.744 65.89,48.421 66.134,48.177 66.377,47.933 66.621,47.689 66.864,47.445 67.108,47.201 67.352,46.957 67.595,46.713 67.839,46.469 68.082,46.225 68.326,45.981 68.57,45.737 68.813,45.493 69.057,45.249 69.301,45.005 69.544,44.761 69.788,44.517 70.031,44.273 70.275,44.029 70.519,43.785 70.762,43.541 71.006,43.297 71.249,43.053 71.493,42.809 71.737,42.565 71.98,42.321 72.224,42.077 72.467,41.833 72.711,41.589 72.955,41.345 73.198,41.101 73.442,40.857 73.685,40.613 73.929,40.369 74.173,40.125 74.416,39.881 74.66,39.637 74.903,39.393 75.147,39.149 75.5,38.8 76.375,38.8 76.606,38.905 76.91,38.905 76.65,38.913 76.391,38.92 76.43,38.92 76.67,39.16 R_DISPLAY_CS.2 77.192,39.4 77.473,39.4 77.755,39.4 78.036,39.4 78.255,39.157 78.3,38.975 78.475,38.8 79.35,38.8 79.593,39.083 79.752,39.242 R_DISPLAY_RESET.2 86.575,39.4 C_OLED_VBAT.1 91.075,46.585 C_OLED_VDD.1 91.588,47.098 91.786,47.296 91.983,47.493 92.181,47.691 92.181,48.025 92.181,48.359 92.181,48.694 v1(92.181,49.028) ; 93.647,48.528 93.876,48.299 94.104,48.071 94.332,47.843 94.56,47.615 94.909,47.615 95.259,47.615 95.608,47.615 95.957,47.615 96.307,47.615 96.656,47.615 97.005,47.615 97.355,47.615 97.704,47.615 98.053,47.615 98.403,47.615 98.752,47.615 99.101,47.615 99.451,47.615 99.8,47.615 100.041,47.374 100.282,47.133 ; 102.025,46.647 102.255,46.646 102.54,46.644 102.7,46.6 102.9,46.8 103.1,47 103.3,47.2 103.15,47.5 103,47.8 102.7,47.95 102.308,48.261
  Bottom w0.35: v1(45.8,63.457) 45.804,63.461 45.804,63.517 48.97,66.683 J_DEBUG.1 ; v1(92.181,49.028) 92.184,49.025 92.401,49.025 92.668,49.025 92.936,49.025 v1(93.203,49.025)
XT2_IN: U_MAIN.69 Y_XT2.1 | length 6.7
  Top w0.15: v1(57.876,46.301) 58.15,46.043 U_MAIN.69 ; v1(59.058,43.599) 59.099,43.539 59.099,43.525 59.4,43.225 Y_XT2.1
  Bottom w0.15: v1(57.876,46.301) 57.978,46.215 57.978,46.159 59.039,45.098 v1(59.058,43.599)
XT2_OUT: U_MAIN.70 Y_XT2.3 | length 3.7
  Top w0.15: Y_XT2.3 56.909,41.9 57.042,42.034 v1(57.069,42.007) ; v1(57.435,42.831) 57.461,44.523 U_MAIN.70
  Bottom w0.15: v1(57.069,42.007) 57.069,42.314 57.382,42.626 57.382,42.752 v1(57.435,42.831)
pads on no net: J_DISPLAY.7 J_DISPLAY.31 J_DISPLAY.32 J_USB.5 J_USB.11 J_USB.NPTH-1 J_USB.NPTH-2 U_LDO.4 U_MAIN.1 U_MAIN.2 U_MAIN.3 U_MAIN.4 U_MAIN.5 U_MAIN.6 U_MAIN.7 U_MAIN.8 U_MAIN.9 U_MAIN.10 U_MAIN.12 U_MAIN.13 U_MAIN.15 U_MAIN.16 U_MAIN.17 U_MAIN.21 U_MAIN.22 U_MAIN.23 U_MAIN.25 U_MAIN.26 U_MAIN.27 U_MAIN.28 U_MAIN.29 U_MAIN.30 U_MAIN.31 U_MAIN.32 U_MAIN.33 U_MAIN.34 U_MAIN.35 U_MAIN.36 U_MAIN.45 U_MAIN.46 U_MAIN.47 U_MAIN.48 U_MAIN.51 U_MAIN.52 U_MAIN.53 U_MAIN.54 U_MAIN.55 U_MAIN.56 U_MAIN.57 U_MAIN.58 U_MAIN.59 U_MAIN.60 U_MAIN.72 U_MAIN.73 U_MAIN.74 U_MAIN.75 U_MAIN.77 U_MAIN.78 U_MAIN.79 U_MAIN.80

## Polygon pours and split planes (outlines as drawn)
GND on Bottom (solid): 107.1,77.1 25.7,77.1 25.7,25.7 107.1,25.7

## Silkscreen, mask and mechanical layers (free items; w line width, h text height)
Top Overlay:
  text "2L • BOTTOM GND POUR" at 48.4,75.4 h0.48
  text "ER-CON30HT-1 • 4-WIRE SPI" at 84.4,75.4 h0.55
  text "ER-OLED096-1-3W" at 81.4,28.9 h0.58
  text "QUICK CONFIGURE • SCREEN" at 66.4,27.4 h0.72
